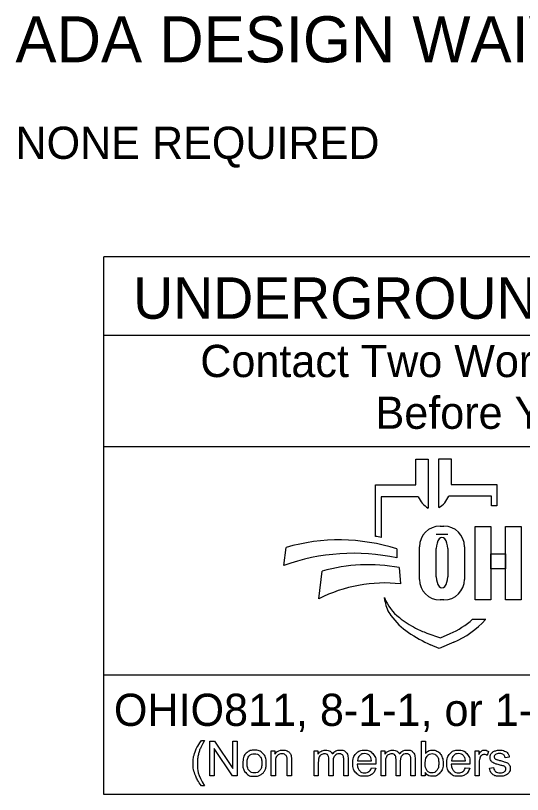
# Model space of a CAD drawing. Extents: x -19.9 to 41.9, y 0 to 32.3.
# Drawn here: x 1.995 to 4.196, y 2.143 to 5.529 of the extents above; entities that cross this region are included whole.
import ezdxf

# ---------------------------------------------------------------- set-up
doc = ezdxf.new("R2010")
doc.units = 0
doc.layers.add('SH_Data', color=7, linetype='Continuous')
doc.layers.add('SH_Text', color=7, linetype='Continuous')

msp = doc.modelspace()

# ---------------------------------------------------------------- linework, layer by layer
at = {"layer": 'SH_Data'}
for p, q in [((2.3775, 2.1428), (2.3775, 4.4803)), ((6.6275, 4.4803), (2.3775, 4.4803)), ((2.3775, 4.1387), (6.6275, 4.1387)), ((2.3775, 3.6553), (6.6275, 3.6553)), ((6.6275, 2.6607), (2.3775, 2.6607)), ((6.6275, 2.1428), (2.3775, 2.1428))]:
    msp.add_line(p, q, dxfattribs=at)
at = {"layer": 'SH_Text'}
for p, q in [((3.7335, 3.4883), (3.7335, 3.5998)), ((3.7335, 3.5998), (3.7872, 3.5998)), ((3.7872, 3.5998), (3.7872, 3.3877)), ((3.8329, 3.39), (3.8329, 3.6021)), ((3.8329, 3.6021), (3.8865, 3.6021)), ((3.8865, 3.6021), (3.8865, 3.4906)), ((3.5576, 3.2644), (3.5576, 3.4883)), ((3.5576, 3.4883), (3.7335, 3.4883)), ((3.8865, 3.4906), (4.0857, 3.4906)), ((4.0857, 3.4906), (4.0857, 3.3968)), ((3.5828, 3.4369), (3.5828, 3.26)), ((3.7439, 3.4369), (3.5828, 3.4369)), ((4.0625, 3.4392), (3.8761, 3.4392)), ((4.0625, 3.3968), (4.0625, 3.4392)), ((4.0857, 3.3968), (4.0625, 3.3968)), ((3.8385, 3.3091), (3.8551, 3.3091)), ((3.8718, 3.2721), (3.822, 3.2721)), ((3.7491, 3.0776), (3.7491, 3.2196)), ((3.9445, 3.2196), (3.9445, 3.0776)), ((3.1602, 3.1381), (3.1696, 3.2162)), ((3.6509, 3.2097), (3.6509, 3.1709)), ((3.822, 3.089), (3.822, 3.2114)), ((3.8718, 3.2114), (3.8718, 3.089)), ((3.6608, 3.1291), (3.6671, 3.0582)), ((3.312, 2.9936), (3.3267, 3.1137)), ((3.5997, 2.9807), (3.5967, 2.9986)), ((3.8551, 2.9882), (3.8385, 2.9882)), ((3.98, 2.9048), (4.0375, 2.9048)), ((3.7816, 2.8444), (3.841, 2.8239)), ((3.841, 2.8239), (3.8821, 2.8417)), ((3.835, 2.7769), (3.7976, 2.7934)), ((3.8983, 2.8044), (3.835, 2.7769))]:
    msp.add_line(p, q, dxfattribs=at)
for points in [[(3.991, 3.3081), (4.0589, 3.3081), (4.0589, 2.9881), (3.991, 2.9881)], [(4.1231, 3.3081), (4.1911, 3.3081), (4.1911, 2.9881), (4.1231, 2.9881)], [(4.0589, 3.1882), (4.1231, 3.1882), (4.1231, 3.1242), (4.0589, 3.1242)]]:
    msp.add_lwpolyline(points, close=True, dxfattribs=at)
for points in [[(2.8021, 2.3766), (2.8153, 2.3766)], [(2.8389, 2.2239), (2.8389, 2.3741), (2.8592, 2.3741), (2.9382, 2.2561), (2.9382, 2.3741), (2.9572, 2.3741), (2.9572, 2.2239), (2.9369, 2.2239), (2.8579, 2.3419), (2.8579, 2.2239), (2.8389, 2.2239)], [(3.7743, 2.2239), (3.7573, 2.2239), (3.7573, 2.3741), (3.7757, 2.3741), (3.7757, 2.3206)], [(3.1048, 2.2239), (3.1048, 2.3328), (3.1214, 2.3328), (3.1214, 2.3173)], [(3.2912, 2.2239), (3.2912, 2.3328), (3.3077, 2.3328), (3.3077, 2.3174)], [(3.5826, 2.2239), (3.5826, 2.3328), (3.5991, 2.3328), (3.5991, 2.3174)], [(3.9904, 2.2239), (3.9904, 2.3328), (4.007, 2.3328), (4.007, 2.3163)], [(4.0495, 2.3293), (4.043, 2.3122)], [(4.1394, 2.3046), (4.1213, 2.3022)], [(3.1233, 2.2833), (3.1233, 2.2239), (3.1048, 2.2239)], [(3.1932, 2.2908), (3.1932, 2.2239), (3.1748, 2.2239), (3.1748, 2.2901)], [(3.3097, 2.2803), (3.3097, 2.2239), (3.2912, 2.2239)], [(3.3743, 2.2871), (3.3743, 2.2239), (3.3559, 2.2239), (3.3559, 2.2946)], [(3.4388, 2.2986), (3.4388, 2.2239), (3.4203, 2.2239), (3.4203, 2.2924)], [(3.56, 2.2736), (3.4788, 2.2736)], [(3.4799, 2.2887), (3.5406, 2.2887)], [(3.601, 2.2803), (3.601, 2.2239), (3.5826, 2.2239)], [(3.6657, 2.2871), (3.6657, 2.2239), (3.6473, 2.2239), (3.6473, 2.2946)], [(3.7301, 2.2986), (3.7301, 2.2239), (3.7117, 2.2239), (3.7117, 2.2924)], [(3.968, 2.2736), (3.8868, 2.2736)], [(3.8879, 2.2887), (3.9486, 2.2887)], [(4.0088, 2.2809), (4.0088, 2.2239), (3.9904, 2.2239)], [(3.5404, 2.2591), (3.5595, 2.2567)], [(3.7743, 2.2375), (3.7743, 2.2239)], [(3.9484, 2.2591), (3.9675, 2.2567)], [(4.053, 2.2564), (4.0712, 2.2593)], [(2.8153, 2.1798), (2.8021, 2.1798)]]:
    msp.add_lwpolyline(points, dxfattribs=at)
for centre, radius, start, end in [((3.8353, 3.4736), 0.0985, 201.9296, 240.7469), ((3.7847, 3.476), 0.0985, 299.2531, 338.0704), ((3.8385, 3.2196), 0.0895, 90, 180), ((3.8551, 3.2196), 0.0895, 0, 90), ((3.4295, 2.4554), 0.8191, 79.2074, 81.0007), ((3.3997, 2.4302), 0.8191, 72.1402, 106.3144), ((3.4628, 2.2991), 0.8919, 77.8238, 109.8274), ((3.5267, 2.4094), 0.7322, 79.44, 105.8467), ((3.5987, 2.4262), 0.6357, 83.8248, 116.8021), ((3.8385, 3.0776), 0.0895, 180, 270), ((3.8551, 3.0776), 0.0895, 270, 0), ((3.7841, 3.0707), 0.2008, 201.0457, 232.5314), ((3.741, 3.0048), 0.1433, 189.6817, 216.0884), ((3.8747, 3.1022), 0.3088, 216.0884, 235.7167), ((3.9766, 3.3219), 0.5173, 232.5314, 241.794), ((3.7387, 3.1722), 0.3602, 293.4582, 312.0712), ((3.7387, 3.1722), 0.401, 293.4582, 317.8286), ((4.0412, 3.3465), 0.6044, 235.7167, 246.2325), ((3.8914, 3.1631), 0.3371, 241.794, 250.9821)]:
    msp.add_arc(centre, radius, start, end, dxfattribs=at)
for centre, start_param, end_param in [((3.8469, 3.2114), 4.712389, 7.853982), ((3.8469, 3.089), 1.570796, 4.712389)]:
    msp.add_ellipse(centre, major_axis=(0, 0.0484), ratio=0.514403, start_param=start_param, end_param=end_param, dxfattribs=at)
for points in [[(2.8021, 2.1798), (2.7869, 2.199), (2.7763, 2.2248), (2.7657, 2.2506), (2.7657, 2.2783), (2.7657, 2.3026), (2.7736, 2.325), (2.7829, 2.3509), (2.8021, 2.3766)], [(2.8153, 2.3766), (2.8029, 2.3553), (2.7989, 2.3462), (2.7927, 2.332), (2.7891, 2.3167), (2.7847, 2.2975), (2.7847, 2.2782), (2.7847, 2.2289), (2.8153, 2.1798)], [(2.9814, 2.2783), (2.9814, 2.3085), (2.9981, 2.3231), (3.0122, 2.3352), (3.0323, 2.3352), (3.0547, 2.3352), (3.069, 2.3205), (3.0832, 2.3058), (3.0832, 2.2799), (3.0832, 2.2589), (3.0769, 2.2469), (3.0706, 2.2348), (3.0586, 2.2282), (3.0466, 2.2215), (3.0323, 2.2215), (3.0095, 2.2215), (2.9954, 2.2362), (2.9814, 2.2508), (2.9814, 2.2783)], [(3.0003, 2.2783), (3.0003, 2.2574), (3.0094, 2.247), (3.0185, 2.2366), (3.0323, 2.2366), (3.046, 2.2366), (3.0551, 2.2471), (3.0642, 2.2575), (3.0642, 2.279), (3.0642, 2.2991), (3.0551, 2.3095), (3.0459, 2.3199), (3.0323, 2.3199), (3.0185, 2.3199), (3.0094, 2.3096), (3.0003, 2.2992), (3.0003, 2.2783)], [(3.1214, 2.3173), (3.1334, 2.3352), (3.156, 2.3352), (3.1659, 2.3352), (3.1741, 2.3316), (3.1823, 2.3281), (3.1864, 2.3224), (3.1905, 2.3166), (3.1922, 2.3087), (3.1932, 2.3036), (3.1932, 2.2908)], [(3.1748, 2.2901), (3.1748, 2.3013), (3.1726, 2.3069), (3.1705, 2.3125), (3.165, 2.3158), (3.1595, 2.3191), (3.1521, 2.3191), (3.1404, 2.3191), (3.1318, 2.3117), (3.1233, 2.3042), (3.1233, 2.2833)], [(3.3077, 2.3174), (3.3128, 2.3254), (3.3214, 2.3303), (3.3299, 2.3352), (3.3407, 2.3352), (3.3528, 2.3352), (3.3606, 2.3301), (3.3683, 2.3251), (3.3715, 2.3161), (3.3844, 2.3352), (3.4051, 2.3352), (3.4213, 2.3352), (3.43, 2.3262), (3.4388, 2.3172), (3.4388, 2.2986)], [(3.3559, 2.2946), (3.3559, 2.3069), (3.3514, 2.313), (3.3469, 2.3191), (3.3366, 2.3191), (3.3288, 2.3191), (3.3222, 2.315), (3.3156, 2.311), (3.3126, 2.3031), (3.3097, 2.2952), (3.3097, 2.2803)], [(3.4203, 2.2924), (3.4203, 2.3035), (3.4185, 2.3083), (3.4168, 2.3132), (3.412, 2.3162), (3.4073, 2.3191), (3.401, 2.3191), (3.3895, 2.3191), (3.3819, 2.3115), (3.3743, 2.3039), (3.3743, 2.2871)], [(3.5595, 2.2567), (3.555, 2.24), (3.5428, 2.2307), (3.5306, 2.2215), (3.5117, 2.2215), (3.4878, 2.2215), (3.4738, 2.2362), (3.4598, 2.2509), (3.4598, 2.2774), (3.4598, 2.3049), (3.474, 2.32), (3.4881, 2.3352), (3.5106, 2.3352), (3.5324, 2.3352), (3.5463, 2.3203), (3.5601, 2.3055), (3.5601, 2.2785), (3.5601, 2.2769), (3.56, 2.2736)], [(3.5406, 2.2887), (3.5394, 2.3025), (3.5337, 2.3094), (3.5249, 2.3201), (3.5108, 2.3201), (3.4981, 2.3201), (3.4894, 2.3115), (3.4808, 2.303), (3.4799, 2.2887)], [(3.5991, 2.3174), (3.6042, 2.3254), (3.6127, 2.3303), (3.6212, 2.3352), (3.6321, 2.3352), (3.6442, 2.3352), (3.6519, 2.3301), (3.6597, 2.3251), (3.6628, 2.3161), (3.6758, 2.3352), (3.6965, 2.3352), (3.7127, 2.3352), (3.7214, 2.3262), (3.7301, 2.3172), (3.7301, 2.2986)], [(3.6473, 2.2946), (3.6473, 2.3069), (3.6428, 2.313), (3.6383, 2.3191), (3.628, 2.3191), (3.6202, 2.3191), (3.6136, 2.315), (3.607, 2.311), (3.604, 2.3031), (3.601, 2.2952), (3.601, 2.2803)], [(3.7117, 2.2924), (3.7117, 2.3035), (3.7099, 2.3083), (3.7081, 2.3132), (3.7034, 2.3162), (3.6987, 2.3191), (3.6923, 2.3191), (3.6809, 2.3191), (3.6733, 2.3115), (3.6657, 2.3039), (3.6657, 2.2871)], [(3.7741, 2.2792), (3.7741, 2.2596), (3.7794, 2.2509), (3.7881, 2.2366), (3.8029, 2.2366), (3.815, 2.2366), (3.8238, 2.2471), (3.8326, 2.2576), (3.8326, 2.2784), (3.8326, 2.2998), (3.8241, 2.3099), (3.8157, 2.3201), (3.8038, 2.3201), (3.7917, 2.3201), (3.7829, 2.3096), (3.7741, 2.299), (3.7741, 2.2792)], [(3.7757, 2.3206), (3.7874, 2.3352), (3.8055, 2.3352), (3.8155, 2.3352), (3.8245, 2.3311), (3.8335, 2.3271), (3.8392, 2.3198), (3.845, 2.3124), (3.8483, 2.3021), (3.8516, 2.2918), (3.8516, 2.28), (3.8516, 2.252), (3.8378, 2.2368), (3.8239, 2.2215), (3.8046, 2.2215), (3.7853, 2.2215), (3.7743, 2.2375)], [(3.9675, 2.2567), (3.963, 2.24), (3.9508, 2.2307), (3.9386, 2.2215), (3.9196, 2.2215), (3.8958, 2.2215), (3.8818, 2.2362), (3.8678, 2.2509), (3.8678, 2.2774), (3.8678, 2.3049), (3.882, 2.32), (3.8961, 2.3352), (3.9186, 2.3352), (3.9404, 2.3352), (3.9543, 2.3203), (3.9681, 2.3055), (3.9681, 2.2785), (3.9681, 2.2769), (3.968, 2.2736)], [(3.9486, 2.2887), (3.9474, 2.3025), (3.9417, 2.3094), (3.9328, 2.3201), (3.9188, 2.3201), (3.9061, 2.3201), (3.8974, 2.3115), (3.8888, 2.303), (3.8879, 2.2887)], [(4.007, 2.3163), (4.0133, 2.3278), (4.0187, 2.3315), (4.0241, 2.3352), (4.0305, 2.3352), (4.0398, 2.3352), (4.0495, 2.3293)], [(4.043, 2.3122), (4.0363, 2.3162), (4.0295, 2.3162), (4.0235, 2.3162), (4.0187, 2.3125), (4.0139, 2.3089), (4.0119, 2.3024), (4.0088, 2.2926), (4.0088, 2.2809)], [(4.1213, 2.3022), (4.1201, 2.3106), (4.1142, 2.3153), (4.1083, 2.3201), (4.0975, 2.3201), (4.0848, 2.3201), (4.0794, 2.3159), (4.0739, 2.3116), (4.0739, 2.306), (4.0739, 2.3024), (4.0762, 2.2995), (4.0785, 2.2966), (4.0833, 2.2946), (4.086, 2.2936), (4.0996, 2.2899), (4.1192, 2.2847), (4.1269, 2.2813), (4.1347, 2.278), (4.1391, 2.2717), (4.1435, 2.2653), (4.1435, 2.2559), (4.1435, 2.2467), (4.1381, 2.2386), (4.1327, 2.2304), (4.1226, 2.226), (4.1124, 2.2215), (4.0996, 2.2215), (4.0784, 2.2215), (4.0672, 2.2303), (4.0561, 2.2391), (4.053, 2.2564)], [(4.0712, 2.2593), (4.0727, 2.2483), (4.0798, 2.2425), (4.0868, 2.2366), (4.0995, 2.2366), (4.1122, 2.2366), (4.1184, 2.2418), (4.1245, 2.247), (4.1245, 2.254), (4.1245, 2.2602), (4.1191, 2.2638), (4.1153, 2.2663), (4.1002, 2.2701), (4.0799, 2.2752), (4.072, 2.2789), (4.0642, 2.2827), (4.0601, 2.2893), (4.0561, 2.2959), (4.0561, 2.3038), (4.0561, 2.3111), (4.0594, 2.3173), (4.0628, 2.3235), (4.0685, 2.3276), (4.0728, 2.3308), (4.0803, 2.333), (4.0877, 2.3352), (4.0962, 2.3352), (4.109, 2.3352), (4.1187, 2.3315), (4.1284, 2.3278), (4.133, 2.3215), (4.1377, 2.3152), (4.1394, 2.3046)], [(3.4788, 2.2736), (3.4799, 2.2557), (3.489, 2.2462), (3.4981, 2.2366), (3.5117, 2.2366), (3.5219, 2.2366), (3.5291, 2.242), (3.5362, 2.2473), (3.5404, 2.2591)], [(3.8868, 2.2736), (3.8879, 2.2557), (3.897, 2.2462), (3.9061, 2.2366), (3.9197, 2.2366), (3.9299, 2.2366), (3.937, 2.242), (3.9442, 2.2473), (3.9484, 2.2591)]]:
    msp.add_open_spline(points, degree=3, dxfattribs=at)

# ---------------------------------------------------------------- texts
for s, height, p in [('ADA DESIGN WAIVERS', 0.2, (1.9944, 5.3256)), ('NONE REQUIRED', 0.14, (1.9944, 4.9056)), ('UNDERGROUND UTILITIES', 0.18, (2.5057, 4.2106)), ('Contact Two Working Days', 0.14, (2.7972, 3.9571)), ('Before You Dig', 0.14, (3.5583, 3.7321)), ('OHIO811, 8-1-1, or 1-800-362-2764', 0.14, (2.422, 2.4406))]:
    msp.add_text(s, height=height, dxfattribs=at).set_placement(p)

doc.saveas('drawing.dxf')
